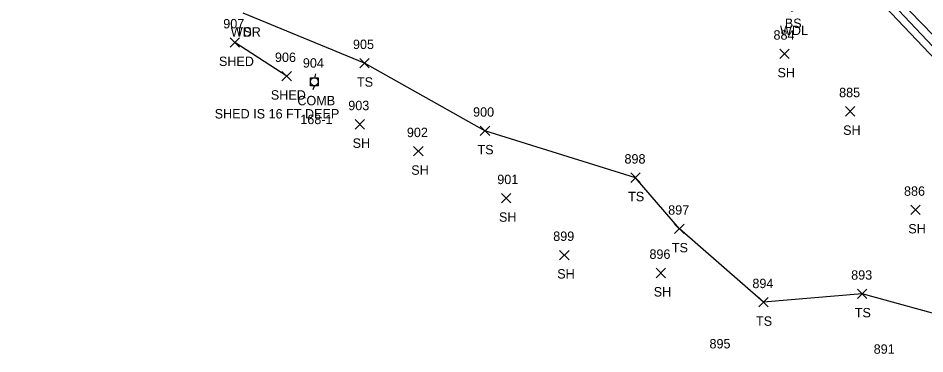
# Model space of a CAD drawing. Extents: x 1879695 to 1880991, y 836466 to 845172.
# Drawn here: x 1879991.4 to 1880183.9, y 844012.2 to 844083.5 of the extents above; entities that cross this region are included whole.
import ezdxf

# ---------------------------------------------------------------- set-up
doc = ezdxf.new("R2010")
doc.units = 0
for name, color, linetype in [('L_A', 7, 'Continuous'), ('L_C', 7, 'Continuous'), ('L_I', 7, 'Continuous'), ('L_TIC', 7, 'Continuous'), ('LAWA', 7, 'Continuous'), ('LBC', 7, 'Continuous'), ('LELB', 7, 'Continuous'), ('U_A', 7, 'Continuous'), ('U_C', 7, 'Continuous'), ('U_I', 7, 'Continuous'), ('UP', 7, 'Continuous')]:
    doc.layers.add(name, color=color, linetype=linetype)

msp = doc.modelspace()

# ---------------------------------------------------------------- linework, layer by layer
at = {"layer": 'L_TIC'}
for points in [[(1880036.43, 844077.36), (1880038.43, 844079.36)], [(1880038.43, 844077.36), (1880036.43, 844079.36)], [(1880153.16, 844074.96), (1880155.16, 844076.96)], [(1880155.16, 844074.96), (1880153.16, 844076.96)], [(1880063.96, 844072.97), (1880065.96, 844074.97)], [(1880065.96, 844072.97), (1880063.96, 844074.97)], [(1880047.45, 844070.22), (1880049.45, 844072.22)], [(1880049.45, 844070.22), (1880047.45, 844072.22)], [(1880167.09, 844062.74), (1880169.09, 844064.74)], [(1880169.09, 844062.74), (1880167.09, 844064.74)], [(1880062.96, 844059.98), (1880064.96, 844061.98)], [(1880064.96, 844059.98), (1880062.96, 844061.98)], [(1880089.54, 844058.6), (1880091.54, 844060.6)], [(1880091.54, 844058.6), (1880089.54, 844060.6)], [(1880075.4, 844054.26), (1880077.4, 844056.26)], [(1880077.4, 844054.26), (1880075.4, 844056.26)], [(1880121.52, 844048.64), (1880123.52, 844050.64)], [(1880123.52, 844048.64), (1880121.52, 844050.64)], [(1880094.04, 844044.28), (1880096.04, 844046.28)], [(1880096.04, 844044.28), (1880094.04, 844046.28)], [(1880180.93, 844041.8), (1880182.93, 844043.8)], [(1880182.93, 844041.8), (1880180.93, 844043.8)], [(1880130.81, 844037.78), (1880132.81, 844039.78)], [(1880132.81, 844037.78), (1880130.81, 844039.78)], [(1880106.4, 844032.21), (1880108.4, 844034.21)], [(1880108.4, 844032.21), (1880106.4, 844034.21)], [(1880126.88, 844028.4), (1880128.88, 844030.4)], [(1880128.88, 844028.4), (1880126.88, 844030.4)], [(1880169.65, 844023.97), (1880171.65, 844025.97)], [(1880171.65, 844023.97), (1880169.65, 844025.97)], [(1880148.68, 844022.18), (1880150.68, 844024.18)], [(1880150.68, 844022.18), (1880148.68, 844024.18)]]:
    msp.add_lwpolyline(points, dxfattribs=at)
at = {"layer": 'LAWA'}
msp.add_lwpolyline([(1880235.36, 844016.97), (1880226.78, 844031.19), (1880215.51, 844044.03), (1880209.22, 844044.19), (1880209.6, 844049.55), (1880199.81, 844058.74), (1880190.2, 844070.4), (1880171.48, 844090.23), (1880169.04, 844093.32), (1880159.9, 844092.48), (1880155.76, 844084.92), (1880148.42, 844091.37), (1880152.26, 844105.95), (1880144.4, 844115.49), (1880125.95, 844132.35), (1880103.11, 844152.62), (1880080.73, 844170.23), (1880061.24, 844186.41), (1880031.89, 844196.39), (1880020.4, 844184.31), (1880005.38, 844176.44), (1879986.51, 844163.82)], dxfattribs=at)
at = {"layer": 'LBC'}
msp.add_lwpolyline([(1880048.45, 844071.22), (1880037.43, 844078.36)], dxfattribs=at)
at = {"layer": 'LELB'}
for points in [[(1880208.14, 844057.06), (1880205.3, 844059.71), (1880199.4, 844059.75), (1880191.54, 844071.18), (1880172.4, 844091.6), (1880168.93, 844094.5), (1880159.81, 844093.84), (1880155.76, 844086.44), (1880150.38, 844091.63), (1880154.09, 844106.65), (1880145.11, 844116.32), (1880126.55, 844133.72), (1880103.74, 844153.59), (1880081.3, 844171.15), (1880062.9, 844187.7), (1880046.08, 844200.5), (1880030.27, 844215.53), (1880015.96, 844231.11), (1880002.51, 844242.73), (1879985.64, 844257.52)], [(1880223.61, 844044.33), (1880209.51, 844057.91), (1880192.94, 844072.51), (1880173.59, 844092.48), (1880156.34, 844108.5), (1880145.52, 844117.21), (1880140.19, 844123.17), (1880127.57, 844134.43), (1880104.95, 844154.51), (1880082.15, 844172.53), (1880063.54, 844188.27), (1880047.18, 844201.5), (1880031.58, 844216.92), (1880015.96, 844231.11)], [(1880205.14, 844013.35), (1880191.21, 844019.31), (1880170.65, 844024.97), (1880149.68, 844023.18), (1880131.81, 844038.78), (1880122.52, 844049.64), (1880090.54, 844059.6), (1880064.96, 844073.97), (1880039.21, 844084.61)]]:
    msp.add_lwpolyline(points, dxfattribs=at)
at = {"layer": 'UP'}
for p, q in [((1880053.49, 844069.18), (1880053.49, 844070.85)), ((1880053.49, 844070.85), (1880055.15, 844070.85)), ((1880054.57, 844071.68), (1880054.32, 844070.85)), ((1880055.15, 844070.85), (1880055.15, 844069.18)), ((1880055.15, 844069.18), (1880053.49, 844069.18)), ((1880054.07, 844068.35), (1880054.32, 844069.18)), ((1880054.32, 844070.02), (1880054.32, 844070.02))]:
    msp.add_line(p, q, dxfattribs=at)
msp.add_circle((1880054.32, 844070.02), 0.833, dxfattribs=at)

# ---------------------------------------------------------------- texts
at = {"layer": 'L_A'}
for s, p in [('WDL', (1880153.18, 844079.92)), ('BS', (1880154.2, 844081.44)), ('WDR', (1880036.57, 844079.61)), ('TS', (1880037.62, 844079.61)), ('SHED', (1880034.06, 844073.36)), ('SH', (1880152.65, 844070.96)), ('TS', (1880063.37, 844068.97)), ('SHED', (1880045.08, 844066.22)), ('SH', (1880166.58, 844058.74)), ('SH', (1880062.45, 844055.98)), ('TS', (1880088.95, 844054.6)), ('SH', (1880074.89, 844050.26)), ('TS', (1880120.93, 844044.64)), ('SH', (1880093.52, 844040.28)), ('SH', (1880180.42, 844037.8)), ('TS', (1880130.22, 844033.78)), ('SH', (1880105.88, 844028.21)), ('SH', (1880126.37, 844024.4)), ('TS', (1880148.09, 844018.18)), ('TS', (1880169.06, 844019.97))]:
    msp.add_text(s, height=2, dxfattribs=at).set_placement(p)
at = {"layer": 'L_C'}
msp.add_text('SHED IS 16 FT DEEP', height=2, dxfattribs=at).set_placement((1880033.16, 844062.22))
at = {"layer": 'L_I'}
for s, p in [('907', (1880034.98, 844081.36)), ('884', (1880151.8, 844078.96)), ('905', (1880062.52, 844076.97)), ('906', (1880045.95, 844074.22)), ('885', (1880165.73, 844066.74)), ('903', (1880061.52, 844063.98)), ('900', (1880088.02, 844062.6)), ('902', (1880073.96, 844058.26)), ('898', (1880120.16, 844052.64)), ('901', (1880093.16, 844048.28)), ('886', (1880179.51, 844045.8)), ('897', (1880129.44, 844041.78)), ('899', (1880105.03, 844036.21)), ('896', (1880125.46, 844032.4)), ('893', (1880168.29, 844027.97)), ('894', (1880147.32, 844026.18)), ('895', (1880138.21, 844013.37)), ('891', (1880173.07, 844012.24))]:
    msp.add_text(s, height=2, dxfattribs=at).set_placement(p)
at = {"layer": 'U_A'}
msp.add_text('COMB', height=2, dxfattribs=at).set_placement((1880050.71, 844065.02))
at = {"layer": 'U_C'}
msp.add_text('168-1', height=2, dxfattribs=at).set_placement((1880051.33, 844061.02))
at = {"layer": 'U_I'}
msp.add_text('904', height=2, dxfattribs=at).set_placement((1880051.88, 844073.02))

doc.saveas('drawing.dxf')
